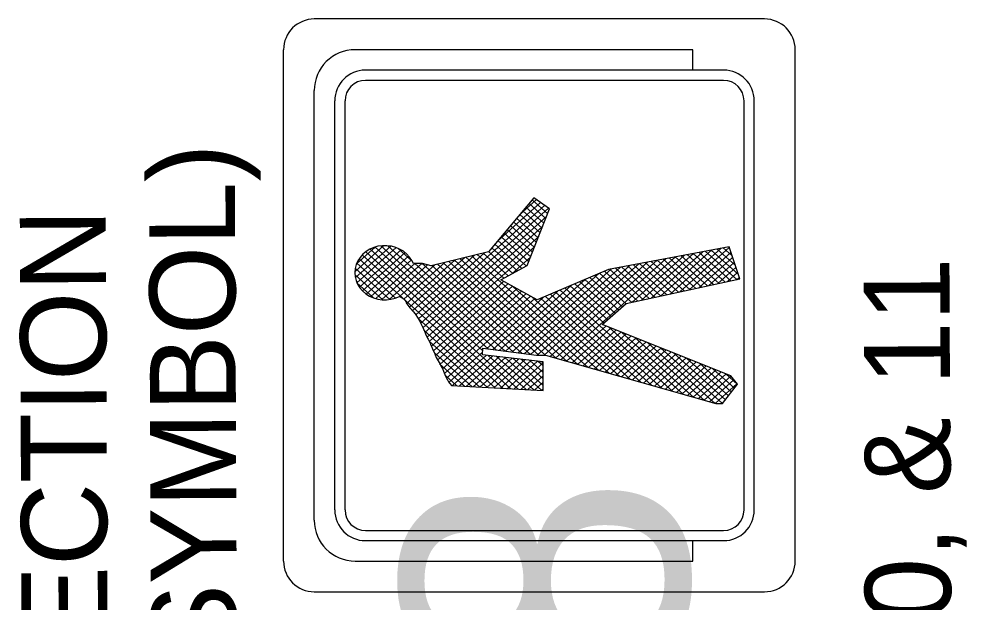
# Model space of a CAD drawing. Extents: x 610543 to 611161, y 419122 to 420064.
# Drawn here: x 610569.3 to 610615.67, y 419403.86 to 419432.36 of the extents above; entities that cross this region are included whole.
import ezdxf

# ---------------------------------------------------------------- set-up
doc = ezdxf.new("R2010")
doc.units = 0
doc.layers.add('C-ANNO-TEXT', color=7, linetype='Continuous')
doc.layers.add('T_Drafting', color=7, linetype='Continuous')

msp = doc.modelspace()

# ---------------------------------------------------------------- linework, layer by layer
at = {"layer": 'T_Drafting'}
for p, q in [((610605.728, 419432.359), (610583.728, 419432.359)), ((610582.228, 419405.859), (610582.228, 419430.859)), ((610602.228, 419430.859), (610585.728, 419430.859)), ((610602.228, 419429.859), (610602.228, 419430.859)), ((610607.228, 419405.859), (610607.228, 419430.859)), ((610603.728, 419429.859), (610586.228, 419429.859)), ((610603.728, 419429.359), (610586.228, 419429.359)), ((610583.728, 419407.859), (610583.728, 419428.859)), ((610584.728, 419408.359), (610584.728, 419428.359)), ((610585.228, 419408.359), (610585.228, 419428.359)), ((610604.728, 419408.359), (610604.728, 419428.359)), ((610605.228, 419408.359), (610605.228, 419428.359)), ((610588.812, 419417.701), (610594.977, 419423.25)), ((610592.659, 419421.482), (610594.779, 419423.39)), ((610593.75, 419422.782), (610594.581, 419423.531)), ((610595.041, 419422.607), (610594.222, 419423.344)), ((610595.134, 419422.842), (610594.374, 419423.526)), ((610588.927, 419417.487), (610595.175, 419423.11)), ((610594.764, 419421.902), (610593.765, 419422.801)), ((610594.857, 419422.137), (610593.917, 419422.982)), ((610594.949, 419422.372), (610594.069, 419423.163)), ((610589.032, 419417.263), (610595.081, 419422.707)), ((610594.487, 419421.197), (610593.309, 419422.257)), ((610594.579, 419421.432), (610593.461, 419422.438)), ((610594.672, 419421.667), (610593.613, 419422.619)), ((610589.133, 419417.036), (610594.887, 419422.215)), ((610594.302, 419420.727), (610593.005, 419421.894)), ((610594.394, 419420.962), (610593.157, 419422.075)), ((610589.237, 419416.812), (610594.694, 419421.722)), ((610593.871, 419420.16), (610592.548, 419421.35)), ((610594.093, 419420.278), (610592.7, 419421.532)), ((610594.209, 419420.492), (610592.853, 419421.713)), ((610585.705, 419419.996), (610587.133, 419421.282)), ((610585.731, 419419.702), (610587.46, 419421.257)), ((610585.783, 419420.385), (610586.701, 419421.211)), ((610585.813, 419419.457), (610587.732, 419421.184)), ((610585.933, 419419.247), (610587.965, 419421.076)), ((610586.086, 419419.067), (610588.166, 419420.938)), ((610593.698, 419414.27), (610586.241, 419420.981)), ((610591.952, 419416.16), (610586.451, 419421.11)), ((610592.225, 419416.231), (610586.694, 419421.209)), ((610592.639, 419416.177), (610586.98, 419421.27)), ((610593.054, 419416.122), (610587.328, 419421.275)), ((610588.498, 419420.541), (610587.825, 419421.147)), ((610588.682, 419417.903), (610592.05, 419420.934)), ((610589.344, 419416.589), (610594.5, 419421.23)), ((610593.206, 419419.803), (610591.972, 419420.915)), ((610593.428, 419419.922), (610592.244, 419420.988)), ((610593.65, 419420.041), (610592.396, 419421.169)), ((610599.718, 419418.608), (610602.264, 419420.899)), ((610600.185, 419418.71), (610602.711, 419420.983)), ((610600.651, 419418.811), (610603.157, 419421.067)), ((610601.118, 419418.913), (610603.604, 419421.15)), ((610601.585, 419419.015), (610604.004, 419421.193)), ((610602.051, 419419.116), (610604.087, 419420.949)), ((610603.799, 419419.497), (610602.246, 419420.896)), ((610604.084, 419419.56), (610602.538, 419420.951)), ((610604.369, 419419.622), (610602.831, 419421.005)), ((610604.453, 419419.864), (610603.123, 419421.06)), ((610604.299, 419420.321), (610603.416, 419421.115)), ((610604.144, 419420.778), (610603.709, 419421.17)), ((610587.696, 419418.717), (610585.799, 419420.425)), ((610592.948, 419414.308), (610585.914, 419420.639)), ((610593.323, 419414.289), (610586.062, 419420.824)), ((610586.269, 419418.913), (610588.336, 419420.773)), ((610586.483, 419418.788), (610588.475, 419420.581)), ((610586.732, 419418.694), (610588.638, 419420.409)), ((610587.025, 419418.639), (610588.987, 419420.405)), ((610588.105, 419418.657), (610590.107, 419420.458)), ((610588.236, 419418.456), (610590.592, 419420.577)), ((610588.382, 419418.27), (610591.078, 419420.696)), ((610588.532, 419418.087), (610591.564, 419420.815)), ((610593.468, 419416.068), (610588.645, 419420.409)), ((610593.882, 419416.013), (610589.003, 419420.405)), ((610595.05, 419415.916), (610590.026, 419420.438)), ((610595.567, 419415.77), (610590.304, 419420.506)), ((610596.083, 419415.623), (610590.582, 419420.574)), ((610596.6, 419415.477), (610590.86, 419420.642)), ((610597.116, 419415.33), (610591.138, 419420.71)), ((610597.632, 419415.183), (610591.416, 419420.779)), ((610592.985, 419419.685), (610591.694, 419420.847)), ((610593.36, 419419.886), (610594.306, 419420.737)), ((610594.611, 419415.921), (610599.586, 419420.398)), ((610594.965, 419415.921), (610600.032, 419420.481)), ((610595.251, 419415.86), (610600.478, 419420.565)), ((610595.519, 419415.783), (610600.925, 419420.648)), ((610595.788, 419415.707), (610601.371, 419420.732)), ((610599.252, 419418.506), (610601.818, 419420.816)), ((610601.238, 419418.939), (610599.612, 419420.402)), ((610601.522, 419419.001), (610599.904, 419420.457)), ((610601.807, 419419.063), (610600.197, 419420.512)), ((610602.092, 419419.125), (610600.49, 419420.567)), ((610602.376, 419419.187), (610600.782, 419420.622)), ((610602.661, 419419.249), (610601.075, 419420.677)), ((610602.945, 419419.311), (610601.368, 419420.731)), ((610603.23, 419419.373), (610601.66, 419420.786)), ((610603.515, 419419.435), (610601.953, 419420.841)), ((610602.518, 419419.218), (610604.169, 419420.704)), ((610602.984, 419419.32), (610604.252, 419420.46)), ((610587.417, 419418.65), (610585.724, 419420.174)), ((610587.386, 419418.646), (610589.267, 419420.338)), ((610587.899, 419418.789), (610589.621, 419420.339)), ((610594.296, 419415.959), (610589.47, 419420.302)), ((610594.692, 419415.921), (610589.748, 419420.37)), ((610593.683, 419416.04), (610598.246, 419420.147)), ((610593.991, 419415.999), (610598.693, 419420.23)), ((610594.3, 419415.958), (610599.139, 419420.314)), ((610599.53, 419418.567), (610597.903, 419420.032)), ((610599.815, 419418.629), (610598.149, 419420.128)), ((610600.099, 419418.691), (610598.441, 419420.183)), ((610600.384, 419418.753), (610598.734, 419420.238)), ((610600.668, 419418.815), (610599.026, 419420.293)), ((610600.953, 419418.877), (610599.319, 419420.348)), ((610603.451, 419419.422), (610604.334, 419420.216)), ((610603.917, 419419.523), (610604.416, 419419.972)), ((610587.08, 419418.635), (610585.707, 419419.871)), ((610589.45, 419416.367), (610592.968, 419419.533)), ((610593.066, 419416.121), (610596.962, 419419.627)), ((610593.374, 419416.08), (610597.639, 419419.918)), ((610598.423, 419417.972), (610596.706, 419419.517)), ((610598.603, 419418.128), (610596.945, 419419.62)), ((610598.783, 419418.285), (610597.185, 419419.723)), ((610598.963, 419418.441), (610597.424, 419419.826)), ((610599.245, 419418.505), (610597.663, 419419.929)), ((610604.384, 419419.625), (610604.499, 419419.728)), ((610586.621, 419418.73), (610585.813, 419419.457)), ((610589.551, 419416.14), (610593.187, 419419.412)), ((610589.649, 419415.909), (610593.407, 419419.292)), ((610589.754, 419415.686), (610593.626, 419419.171)), ((610589.87, 419415.472), (610593.846, 419419.05)), ((610592.449, 419416.202), (610595.609, 419419.046)), ((610592.757, 419416.161), (610596.286, 419419.337)), ((610598.149, 419415.037), (610593.445, 419419.271)), ((610601.248, 419414.157), (610595.749, 419419.106)), ((610597.884, 419417.503), (610595.988, 419419.209)), ((610598.064, 419417.659), (610596.227, 419419.312)), ((610598.244, 419417.815), (610596.467, 419419.415)), ((610589.987, 419415.259), (610594.065, 419418.93)), ((610590.09, 419415.033), (610594.285, 419418.809)), ((610590.19, 419414.806), (610594.504, 419418.688)), ((610592.141, 419416.243), (610594.932, 419418.755)), ((610598.665, 419414.89), (610594.353, 419418.771)), ((610599.182, 419414.744), (610594.792, 419418.695)), ((610599.698, 419414.597), (610595.031, 419418.798)), ((610600.215, 419414.45), (610595.27, 419418.9)), ((610600.731, 419414.304), (610595.51, 419419.003)), ((610592.573, 419414.328), (610588.798, 419417.725)), ((610592.198, 419414.347), (610589.082, 419417.152)), ((610596.057, 419415.631), (610597.968, 419417.35)), ((610596.326, 419415.554), (610598.212, 419417.253)), ((610596.594, 419415.478), (610598.457, 419417.155)), ((610601.764, 419414.011), (610598.122, 419417.289)), ((610596.863, 419415.402), (610598.702, 419417.057)), ((610597.132, 419415.326), (610598.947, 419416.959)), ((610597.401, 419415.249), (610599.192, 419416.862)), ((610597.67, 419415.173), (610599.437, 419416.764)), ((610602.28, 419413.864), (610598.757, 419417.035)), ((610602.797, 419413.718), (610599.392, 419416.782)), ((610591.822, 419414.367), (610589.337, 419416.603)), ((610597.938, 419415.097), (610599.682, 419416.666)), ((610598.207, 419415.02), (610599.927, 419416.568)), ((610598.476, 419414.944), (610600.172, 419416.471)), ((610598.745, 419414.868), (610600.417, 419416.373)), ((610599.013, 419414.791), (610600.662, 419416.275)), ((610603.313, 419413.571), (610600.027, 419416.528)), ((610603.679, 419413.56), (610600.662, 419416.275)), ((610591.447, 419414.386), (610589.583, 419416.064)), ((610590.32, 419414.604), (610591.948, 419416.07)), ((610590.487, 419414.436), (610592.141, 419415.925)), ((610590.821, 419414.419), (610592.453, 419415.887)), ((610591.155, 419414.401), (610592.765, 419415.85)), ((610591.49, 419414.384), (610593.077, 419415.813)), ((610591.824, 419414.367), (610593.389, 419415.776)), ((610594.073, 419414.25), (610592.224, 419415.915)), ((610594.448, 419414.231), (610592.631, 419415.866)), ((610594.824, 419414.211), (610593.039, 419415.817)), ((610594.914, 419414.449), (610593.447, 419415.769)), ((610599.282, 419414.715), (610600.907, 419416.177)), ((610599.551, 419414.639), (610601.152, 419416.08)), ((610599.82, 419414.563), (610601.397, 419415.982)), ((610600.089, 419414.486), (610601.642, 419415.884)), ((610600.357, 419414.41), (610601.887, 419415.786)), ((610603.824, 419413.748), (610601.298, 419416.021)), ((610603.968, 419413.936), (610601.933, 419415.768)), ((610591.072, 419414.406), (610589.853, 419415.503)), ((610592.158, 419414.349), (610593.701, 419415.738)), ((610592.493, 419414.332), (610594.013, 419415.701)), ((610592.827, 419414.315), (610594.326, 419415.664)), ((610593.161, 419414.297), (610594.638, 419415.626)), ((610593.495, 419414.28), (610594.912, 419415.555)), ((610594.913, 419414.767), (610593.854, 419415.72)), ((610594.913, 419415.086), (610594.262, 419415.671)), ((610594.912, 419415.404), (610594.67, 419415.622)), ((610594.908, 419415.537), (610594.848, 419415.591)), ((610600.626, 419414.334), (610602.132, 419415.689)), ((610600.895, 419414.257), (610602.377, 419415.591)), ((610601.164, 419414.181), (610602.621, 419415.493)), ((610601.432, 419414.105), (610602.866, 419415.395)), ((610601.701, 419414.029), (610603.111, 419415.298)), ((610604.113, 419414.124), (610602.568, 419415.515)), ((610590.697, 419414.425), (610590.12, 419414.944)), ((610593.83, 419414.263), (610594.912, 419415.237)), ((610594.164, 419414.245), (610594.913, 419414.919)), ((610601.97, 419413.952), (610603.356, 419415.2)), ((610602.239, 419413.876), (610603.601, 419415.102)), ((610602.508, 419413.8), (610603.846, 419415.004)), ((610602.776, 419413.723), (610604.088, 419414.904)), ((610604.258, 419414.312), (610603.203, 419415.261)), ((610604.402, 419414.5), (610603.838, 419415.008)), ((610604.089, 419414.9), (610604.089, 419414.9)), ((610594.498, 419414.228), (610594.913, 419414.602)), ((610603.045, 419413.647), (610604.237, 419414.72)), ((610603.314, 419413.571), (610604.387, 419414.537)), ((610594.833, 419414.211), (610594.914, 419414.284)), ((610603.655, 419413.559), (610603.732, 419413.629)), ((610603.671, 419413.549), (610603.671, 419413.576)), ((610586.228, 419407.359), (610603.728, 419407.359)), ((610586.228, 419406.859), (610603.728, 419406.859)), ((610602.228, 419405.859), (610602.228, 419406.859)), ((610585.728, 419405.859), (610602.228, 419405.859)), ((610583.728, 419404.359), (610605.728, 419404.359))]:
    msp.add_line(p, q, dxfattribs=at)
msp.add_lwpolyline([(610590.426, 419414.439), (610594.914, 419414.207), (610594.912, 419415.593), (610591.943, 419415.948), (610591.956, 419416.267), (610594.586, 419415.921), (610595.033, 419415.921), (610603.355, 419413.559), (610603.679, 419413.56), (610604.409, 419414.509), (610604.083, 419414.91), (610597.79, 419417.421), (610598.966, 419418.444), (610604.523, 419419.655), (610603.994, 419421.223), (610598.112, 419420.121), (610594.624, 419418.623), (610592.836, 419419.605), (610594.134, 419420.301), (610595.225, 419423.075), (610594.454, 419423.621), (610592.237, 419420.98), (610589.434, 419420.293), (610589.021, 419420.405), (610588.57, 419420.409), (610588.494, 419420.549)], dxfattribs=at)
for centre, radius, start, end in [((610583.728, 419430.859), 1.5, 90, 180), ((610605.728, 419430.859), 1.5, 0, 90), ((610585.728, 419428.859), 2, 90, 180), ((610586.228, 419428.359), 1.5, 90, 180), ((610603.728, 419428.359), 1.5, 0, 90), ((610586.228, 419428.359), 1, 90, 180), ((610603.728, 419428.359), 1, 0, 90), ((610586.228, 419408.359), 1.5, 180, 270), ((610586.228, 419408.359), 1, 180, 270), ((610603.728, 419408.359), 1.5, 270, 360), ((610603.728, 419408.359), 1, 270, 360), ((610585.728, 419407.859), 2, 180, 270), ((610583.728, 419405.859), 1.5, 180, 270), ((610605.728, 419405.859), 1.5, 270, 360)]:
    msp.add_arc(centre, radius, start, end, dxfattribs=at)
msp.add_ellipse((610587.176, 419419.957), major_axis=(1.472, 0), ratio=0.9, start_param=0.463156, end_param=5.216339, dxfattribs=at)
msp.add_spline([(610587.887, 419418.797), (610588.127, 419418.643), (610588.253, 419418.432), (610588.456, 419418.177), (610588.692, 419417.89), (610589.229, 419416.828), (610589.473, 419416.317), (610589.69, 419415.817), (610590.044, 419415.151), (610590.176, 419414.828), (610590.426, 419414.439)], degree=3, dxfattribs=at)

# ---------------------------------------------------------------- texts
at = {"layer": 'C-ANNO-TEXT'}
for s, p in [('(SOLID SYMBOL)', (610580.036, 419380.71)), ('ONE SECTION ', (610573.7, 419384.403)), ('8, 9, 10, & 11', (610614.908, 419387.289))]:
    msp.add_text(s, height=4.2, rotation=90.2455, dxfattribs=at).set_placement(p)
at = {"layer": 'T_Drafting'}
msp.add_text('88', height=14, rotation=90.072, dxfattribs=at).set_placement((610602.007, 419389.324))

doc.saveas('drawing.dxf')
